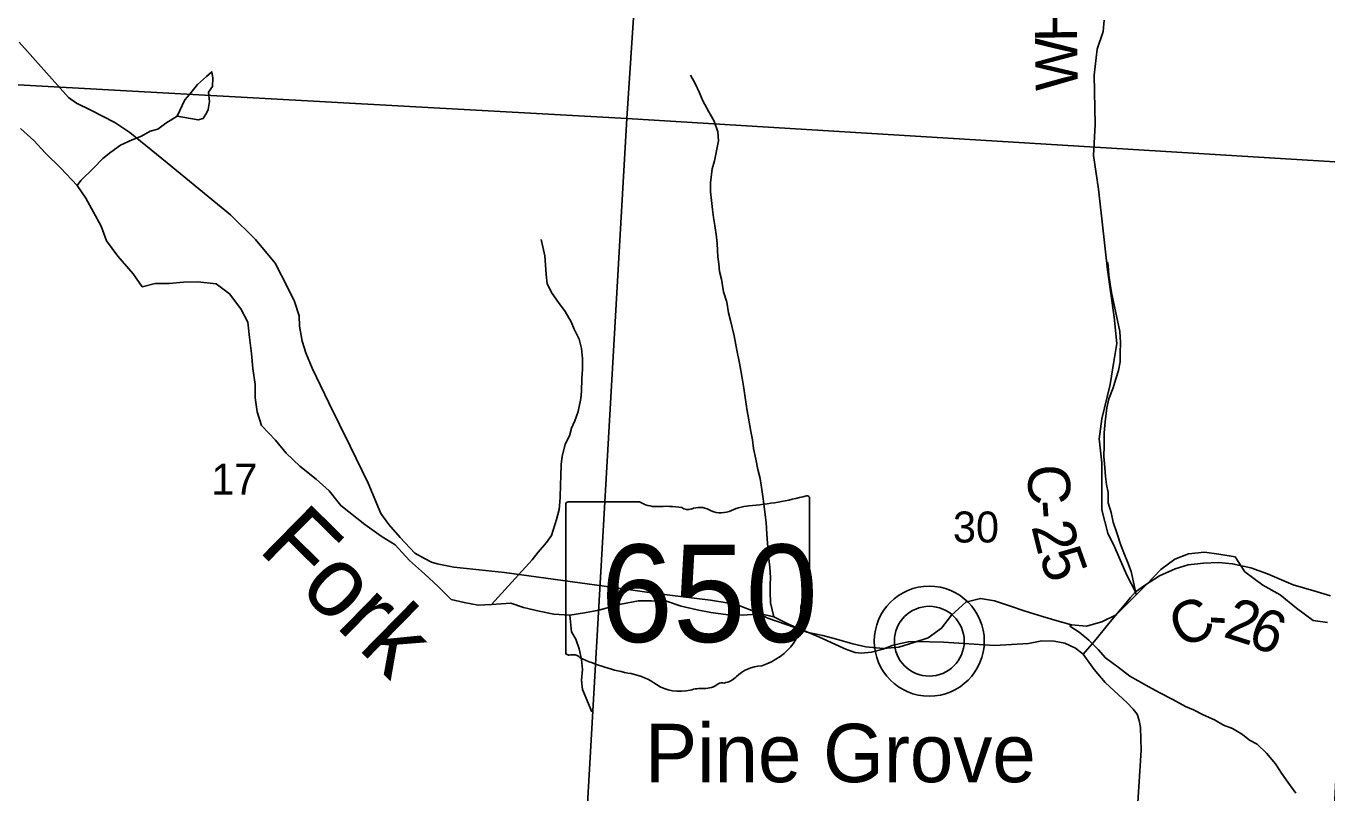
# Model space of a CAD drawing. Extents: x 0 to 44, y -23.8 to 22.
# Drawn here: x 5.562 to 7.321, y 15.535 to 16.572 of the extents above; entities that cross this region are included whole.
import ezdxf

# ---------------------------------------------------------------- set-up
doc = ezdxf.new("R2010")
doc.units = 0
for name, color, linetype in [('GM_X_County_Road', 7, 'Continuous'), ('GM_X_County_Road_Text', 7, 'Continuous'), ('GM_X_Minor_Lake', 7, 'Continuous'), ('GM_X_Minor_River', 7, 'Continuous'), ('GM_X_Minor_River_Text', 7, 'Continuous'), ('GM_X_Section', 7, 'Continuous'), ('GM_X_Section_Text', 7, 'Continuous'), ('GM_X_State_Route', 7, 'Continuous'), ('GM_X_State_Shield', 7, 'Continuous'), ('GM_X_Unincorporated', 7, 'Continuous'), ('GM_X_Unincorporated_Location', 7, 'Continuous'), ('GM_X_Unincorporated_Text', 7, 'Continuous')]:
    doc.layers.add(name, color=color, linetype=linetype)

msp = doc.modelspace()

# ---------------------------------------------------------------- linework, layer by layer
at = {"layer": 'GM_X_County_Road'}
for points in [[(7.0559, 15.799), (7.0626, 15.8066), (7.0508, 15.8292), (7.0343, 15.8667), (7.0251, 15.8862), (7.0169, 15.9176), (7.017, 15.9811), (7.0134, 16.0137), (7.017, 16.0407), (7.0283, 16.0873), (7.033, 16.1184), (7.0374, 16.1427), (7.0334, 16.178), (7.0247, 16.2423), (7.0186, 16.2951), (7.0126, 16.3513), (7.0056, 16.3969), (7.0078, 16.4387), (7.0067, 16.5055), (7.0104, 16.5404), (7.0185, 16.5643), (7.0201, 16.5799)], [(7.0626, 15.8066), (7.0758, 15.8162), (7.0947, 15.8283), (7.1159, 15.8378), (7.1336, 15.8431), (7.1546, 15.8457), (7.1746, 15.8463), (7.1937, 15.8447), (7.2186, 15.8391), (7.2409, 15.831), (7.2756, 15.8163), (7.3035, 15.808), (7.3263, 15.8012)], [(6.9919, 15.7223), (7.0072, 15.7399), (7.0283, 15.7662), (7.0499, 15.7921), (7.0559, 15.799)]]:
    msp.add_lwpolyline(points, dxfattribs=at)
at = {"layer": 'GM_X_Minor_Lake'}
for points in [[(5.8142, 16.4903), (5.815, 16.5013), (5.8135, 16.51), (5.8063, 16.5036), (5.8021, 16.5002), (5.7942, 16.493), (5.7835, 16.4794), (5.7771, 16.4719), (5.7666, 16.4501)], [(5.7666, 16.4501), (5.7948, 16.4449), (5.8016, 16.4467), (5.8066, 16.4551), (5.8085, 16.4592), (5.8104, 16.4698), (5.8089, 16.4824), (5.8142, 16.4903)]]:
    msp.add_lwpolyline(points, dxfattribs=at)
at = {"layer": 'GM_X_Minor_River'}
for points in [[(6.5732, 15.773), (6.5689, 15.7918), (6.5685, 15.8069), (6.5685, 15.8164), (6.5689, 15.8263), (6.5682, 15.8399), (6.5667, 15.8513), (6.5648, 15.8725), (6.564, 15.8847), (6.5629, 15.9006), (6.5591, 15.9324), (6.5576, 15.9419), (6.555, 15.9598), (6.5519, 15.9723), (6.5489, 15.9863), (6.5459, 16.0007), (6.5444, 16.0121), (6.5421, 16.0235), (6.5391, 16.0417), (6.5372, 16.0515), (6.5346, 16.0697), (6.5327, 16.0822), (6.5304, 16.0959), (6.5289, 16.1061), (6.527, 16.116), (6.5232, 16.1334), (6.5199, 16.1528), (6.5149, 16.1736), (6.5123, 16.1839), (6.51, 16.1983), (6.5055, 16.2123), (6.5025, 16.2297), (6.4998, 16.24), (6.4991, 16.2502), (6.4976, 16.2597), (6.4968, 16.2775), (6.4961, 16.287), (6.4938, 16.3022), (6.4919, 16.3128), (6.4904, 16.3238), (6.4893, 16.3359), (6.4878, 16.3477), (6.4878, 16.3598), (6.49, 16.3788), (6.4934, 16.3898), (6.4961, 16.4031), (6.4984, 16.4167), (6.4976, 16.4288), (6.4927, 16.4433), (6.4855, 16.4558), (6.4776, 16.4709), (6.473, 16.4815), (6.467, 16.4944), (6.4607, 16.5056)], [(5.6312, 16.3564), (5.6365, 16.3632), (5.6535, 16.3795), (5.666, 16.3928), (5.677, 16.4015), (5.6902, 16.411), (5.7057, 16.4178), (5.7185, 16.4228), (5.7303, 16.4296), (5.7405, 16.4326), (5.7514, 16.4406), (5.7666, 16.4501)], [(5.5549, 16.4333), (5.5726, 16.417), (5.5885, 16.3998), (5.6093, 16.3797), (5.6312, 16.3564), (5.6432, 16.3389), (5.664, 16.3013), (5.6711, 16.2815), (5.6866, 16.2606), (5.707, 16.2366), (5.7194, 16.2191), (5.7368, 16.2236), (5.7558, 16.2236), (5.7751, 16.2255), (5.7944, 16.2259), (5.8194, 16.2232), (5.8375, 16.2098), (5.8526, 16.1893), (5.862, 16.1714), (5.8646, 16.1509), (5.8672, 16.1292), (5.8691, 16.1087), (5.872, 16.087), (5.872, 16.0691), (5.875, 16.0501), (5.8806, 16.0315), (5.8995, 16.0117), (5.9138, 15.9942), (5.9324, 15.9767), (5.9547, 15.9592), (5.972, 15.9435), (5.9879, 15.9234), (6.0204, 15.8979), (6.0423, 15.8819), (6.0612, 15.8701), (6.0808, 15.8491), (6.1009, 15.8312)], [(6.1916, 15.7897), (6.2465, 15.85), (6.2548, 15.8606), (6.2662, 15.8735), (6.273, 15.883), (6.2794, 15.9046), (6.2832, 15.9183), (6.2843, 15.9338), (6.2851, 15.952), (6.2855, 15.9627), (6.2858, 15.9793), (6.2873, 15.9896), (6.2911, 16.0066), (6.2972, 16.0176), (6.2998, 16.0279), (6.3044, 16.0381), (6.3089, 16.0506), (6.3123, 16.0681), (6.3134, 16.0783), (6.3138, 16.0946), (6.3146, 16.1079), (6.3146, 16.1223), (6.3135, 16.1356), (6.3101, 16.1485), (6.3036, 16.1618), (6.2995, 16.172), (6.2912, 16.186), (6.2821, 16.1978), (6.2738, 16.2103), (6.267, 16.2232), (6.2655, 16.2357), (6.2647, 16.249), (6.2636, 16.2611), (6.2609, 16.2732), (6.2587, 16.2831)], [(7.0634, 15.8029), (7.0606, 15.8156), (7.0565, 15.8342), (7.0516, 15.8475), (7.0475, 15.8574), (7.0426, 15.8699), (7.0374, 15.8867), (7.0321, 15.9011), (7.0295, 15.914), (7.0254, 15.9269), (7.0254, 15.9409), (7.0231, 15.9519), (7.022, 15.9629), (7.0209, 15.9751), (7.0198, 15.9899), (7.0199, 16.0047), (7.0203, 16.0217), (7.0215, 16.0365), (7.0238, 16.0558), (7.0265, 16.0676), (7.0322, 16.0824), (7.036, 16.0949), (7.0394, 16.1062), (7.0417, 16.1176), (7.0418, 16.1293), (7.0422, 16.1441), (7.0411, 16.1589), (7.034, 16.1927), (7.0306, 16.2094), (7.0284, 16.2227), (7.0265, 16.2352), (7.0254, 16.2481), (7.0247, 16.253)], [(6.1009, 15.8312), (6.1197, 15.8141), (6.1371, 15.7966), (6.1549, 15.7924), (6.1738, 15.7886), (6.1916, 15.7897), (6.2177, 15.7916), (6.2351, 15.7855), (6.2563, 15.7805), (6.276, 15.7767), (6.2976, 15.7752), (6.3173, 15.7782), (6.337, 15.782), (6.3665, 15.7903), (6.3904, 15.7948), (6.4082, 15.7944), (6.4282, 15.794), (6.4479, 15.7872), (6.4698, 15.7822), (6.4884, 15.7788), (6.5115, 15.7757), (6.5311, 15.7753), (6.5557, 15.7772), (6.5732, 15.773), (6.5924, 15.7635), (6.6182, 15.7524), (6.6397, 15.7475), (6.6583, 15.7429), (6.6802, 15.7364), (6.698, 15.7322), (6.7214, 15.7299), (6.7426, 15.7321), (6.7627, 15.7382), (6.782, 15.7447), (6.8002, 15.7576), (6.8135, 15.7754), (6.8329, 15.7929), (6.853, 15.7978), (6.8719, 15.7944), (6.8919, 15.7879), (6.9131, 15.7807), (6.9369, 15.7734), (6.9566, 15.7677), (6.9759, 15.762), (6.996, 15.7604), (7.0168, 15.7661), (7.0365, 15.7756), (7.0566, 15.7961), (7.0771, 15.8166), (7.0968, 15.8371), (7.1158, 15.8508), (7.134, 15.858), (7.1556, 15.8603), (7.1749, 15.8576), (7.1972, 15.8542), (7.2104, 15.834), (7.2346, 15.8157), (7.258, 15.8028), (7.2803, 15.7845), (7.3026, 15.7681), (7.3219, 15.7655)], [(6.2976, 15.7752), (6.2998, 15.7526), (6.3058, 15.7427), (6.3103, 15.7298), (6.3134, 15.7154), (6.3145, 15.7018), (6.3134, 15.6873), (6.3145, 15.6748), (6.3273, 15.6445)], [(6.9759, 15.762), (6.9738, 15.7605), (6.9862, 15.7522), (6.9995, 15.7412), (7.0119, 15.7287), (7.0218, 15.7173), (7.0388, 15.7048), (7.0546, 15.6926), (7.066, 15.6866), (7.0803, 15.6783), (7.0943, 15.6707), (7.1128, 15.6612), (7.1302, 15.6517), (7.1408, 15.6472), (7.154, 15.6404), (7.1692, 15.6336), (7.1816, 15.6264), (7.1937, 15.6218), (7.207, 15.6139), (7.2168, 15.6063), (7.227, 15.6006), (7.2395, 15.5885), (7.2519, 15.5741), (7.2599, 15.5615), (7.2686, 15.5494), (7.2791, 15.5343)]]:
    msp.add_lwpolyline(points, dxfattribs=at)
at = {"layer": 'GM_X_Section'}
for points in [[(5.4377, 17.5257), (6.4419, 17.4633), (6.3745, 16.447), (5.3718, 16.5024)], [(6.4419, 17.4633), (7.4446, 17.3999), (7.376, 16.3855), (6.3745, 16.447)], [(5.3718, 16.5024), (6.3745, 16.447), (6.3163, 15.4337), (5.3182, 15.5035)], [(6.3745, 16.447), (7.376, 16.3855), (7.3239, 15.368), (6.3163, 15.4337)]]:
    msp.add_lwpolyline(points, close=True, dxfattribs=at)
at = {"layer": 'GM_X_State_Route'}
for points in [[(6.9919, 15.7223), (6.9812, 15.7307), (6.9668, 15.7372), (6.9524, 15.74), (6.936, 15.7403), (6.9177, 15.7369), (6.8716, 15.7341), (6.8029, 15.7386), (6.7658, 15.7398), (6.7554, 15.7393), (6.7445, 15.7369), (6.7334, 15.734), (6.7214, 15.7294), (6.7056, 15.7252), (6.6915, 15.7236), (6.6834, 15.7246), (6.6717, 15.7289), (6.6352, 15.7454), (6.6147, 15.7538), (6.5651, 15.7711), (6.5457, 15.7804), (6.5274, 15.7878), (6.5099, 15.792), (6.4876, 15.7956), (6.4474, 15.8003), (6.408, 15.8054), (6.3671, 15.8111), (6.2094, 15.833), (6.1409, 15.84), (6.1184, 15.8444), (6.1103, 15.847), (6.1011, 15.8518), (6.0882, 15.8592), (6.0683, 15.8802), (6.0529, 15.8977), (6.042, 15.9128), (6.0248, 15.9535), (6.0006, 16.0037), (5.9719, 16.0622), (5.9493, 16.1092), (5.9404, 16.1301), (5.9355, 16.1458), (5.9322, 16.166), (5.9318, 16.1798), (5.9254, 16.1992), (5.9169, 16.2171), (5.8992, 16.2512), (5.8725, 16.2832), (5.8387, 16.3166), (5.7533, 16.3869), (5.7025, 16.4278), (5.6825, 16.4416), (5.6498, 16.4581), (5.6304, 16.4678), (5.6198, 16.4752), (5.553, 16.55)], [(7.0607, 15.4441), (7.0699, 15.5926), (7.0691, 15.6233), (7.0676, 15.6327), (7.0649, 15.6415), (7.0595, 15.6481), (7.0514, 15.6568), (7.0216, 15.684), (7.0066, 15.7015), (6.9919, 15.7223)]]:
    msp.add_lwpolyline(points, dxfattribs=at)
at = {"layer": 'GM_X_State_Shield'}
for p, q in [((6.292, 15.9249), (6.292, 15.7248)), ((6.3918, 15.9284), (6.2953, 15.9284)), ((6.6216, 15.8286), (6.6216, 15.9333)), ((6.6216, 15.8287), (6.6216, 15.8286))]:
    msp.add_line(p, q, dxfattribs=at)
for centre, major_axis, start_param, end_param in [((6.2958, 15.9253), (0.00382, 0), 1.712693, 3.28349), ((6.4148, 15.9516), (0.037, 0), 4.042523, 4.731795), ((6.4271, 15.816), (0.133, 0), 1.404758, 1.657858), ((6.4573, 15.9264), (0.0107, 0), 3.836095, 5.185415), ((6.4729, 15.9032), (0.0222, 0), 0.950623, 2.079405), ((6.5488, 15.8672), (0.0703, 0), 1.699011, 2.107814), ((6.5042, 16.2012), (0.3495, 0), 4.814394, 5.042369), ((6.618, 15.9337), (0.00367, 0), 6.141152, 7.989035), ((6.5016, 15.935), (0.0267, 0), 4.081561, 5.145723), ((6.6208, 15.8209), (0.00568, 0), 1.883978, 3.671073), ((6.5847, 15.8077), (0.0341, 0), 5.934695, 6.695948), ((6.6177, 15.8282), (0.00393, 0), 5.05454, 6.418171), ((6.6348, 15.7848), (0.0248, 0), 2.387724, 3.262537), ((6.5238, 15.7715), (0.0874, 0), 5.101752, 6.440018), ((6.2959, 15.7244), (0.00385, 0), 3.00124, 4.508301), ((6.2964, 15.7448), (0.0294, 0), 4.665946, 4.897461), ((6.3025, 15.7132), (0.0106, 0), 0.519207, 1.627899), ((6.4363, 15.893), (0.2524, 0), 4.195997, 4.488961), ((6.361, 15.6349), (0.079, 0), 0.823519, 1.323587), ((6.5, 15.7054), (0.0282, 0), 4.937069, 5.64225), ((6.5607, 15.6686), (0.0479, 0), 1.647645, 2.488434), ((6.4464, 15.7123), (0.0501, 0), 4.026481, 4.996735), ((6.4754, 15.6431), (0.0412, 0), 1.495662, 1.94098), ((6.4791, 15.6973), (0.0267, 0), 4.691044, 5.507374), ((6.5032, 15.6779), (0.00752, 0), 1.147584, 2.315152)]:
    msp.add_ellipse(centre, major_axis=major_axis, ratio=0.8, start_param=start_param, end_param=end_param, dxfattribs=at)
at = {"layer": 'GM_X_Unincorporated'}
for radius in [0.0744, 0.0472]:
    msp.add_circle((6.7836, 15.74), radius, dxfattribs=at)
at = {"layer": 'GM_X_Unincorporated_Location'}
msp.add_line((6.7836, 15.74), (6.7836, 15.74), dxfattribs=at)

# ---------------------------------------------------------------- texts
at = {"layer": 'GM_X_County_Road_Text'}
for s, rotation, p in [('H', 90.8561, (6.9835, 16.5506)), ('W', 90.8632, (6.9845, 16.4848)), ('C', 271.7566, (6.9165, 15.9783)), ('-', 274.1186, (6.918, 15.9291)), ('2', 283.9778, (6.9214, 15.8953)), ('5', 289.514, (6.9316, 15.8556)), ('C', 23.8061, (7.1241, 15.7296)), ('2', 342.1468, (7.1794, 15.7465)), ('6', 337.8005, (7.2116, 15.7361)), ('-', 356.485, (7.1598, 15.7472))]:
    msp.add_text(s, height=0.0568, rotation=rotation, dxfattribs=at).set_placement(p)
at = {"layer": 'GM_X_Minor_River_Text'}
msp.add_text('Fork', height=0.09469, rotation=315.4945, dxfattribs=at).set_placement((5.8745, 15.8634))
at = {"layer": 'GM_X_Section_Text'}
for s, p in [('17', (5.8127, 15.9382)), ('30', (6.8156, 15.8735))]:
    msp.add_text(s, height=0.04186, rotation=0, dxfattribs=at).set_placement(p)
at = {"layer": 'GM_X_State_Shield'}
msp.add_text('650', height=0.13184, dxfattribs=at).set_placement((6.339, 15.7389))
at = {"layer": 'GM_X_Unincorporated_Text'}
msp.add_text('Pine Grove', height=0.07898, rotation=0, dxfattribs=at).set_placement((6.3993, 15.5493))

doc.saveas('drawing.dxf')
